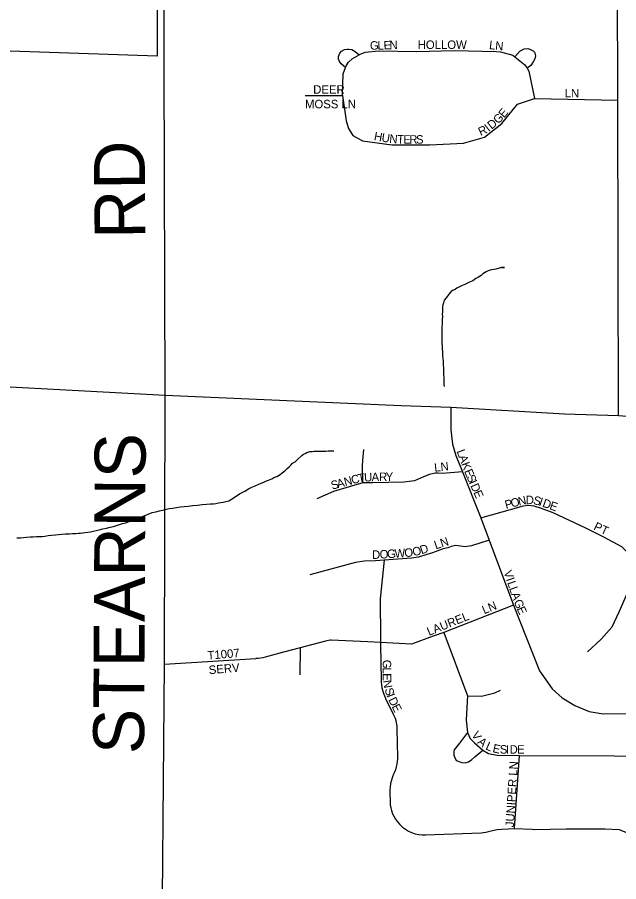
# Model space of a CAD drawing. Extents: x 2010165 to 2382125, y 1060529 to 1407316.
# Drawn here: x 2120255 to 2123802, y 1230221 to 1235321 of the extents above; entities that cross this region are included whole.
import ezdxf

# ---------------------------------------------------------------- set-up
doc = ezdxf.new("R2010")
doc.units = 0
for name, color, linetype in [('GM_X_Corporation', 7, 'Continuous'), ('GM_X_County_Road', 7, 'Continuous'), ('GM_X_County_Road_Text', 7, 'Continuous'), ('GM_X_Minor_River', 7, 'Continuous'), ('GM_X_Township_Subdivision', 7, 'Continuous'), ('GM_X_Township_Subdivision_Text', 7, 'Continuous')]:
    doc.layers.add(name, color=color, linetype=linetype)

msp = doc.modelspace()

# ---------------------------------------------------------------- linework, layer by layer
at = {"layer": 'GM_X_Corporation'}
msp.add_lwpolyline([(2132680.2, 1238887), (2124751.5, 1238922.2), (2124734, 1236210.6), (2124291.4, 1236212.5), (2123784.7, 1236210.1), (2121079.3, 1236231.2), (2121079, 1235091.9), (2120094.3, 1235126), (2120087.8, 1234155), (2113849.1, 1234218.1), (2113890.9, 1243217.2), (2116730.1, 1243190.3), (2116750.2, 1244175.2), (2120503.3, 1244150.8), (2120624.6, 1245916.3), (2121435.6, 1245924.1), (2121430.7, 1248710), (2122369.9, 1248724.5), (2122407.5, 1248826.9), (2123195.5, 1249602.9), (2123111, 1249688.7), (2124088.2, 1249725.4), (2124149.1, 1251538.9), (2132230.3, 1251466.2)], dxfattribs=at)
at = {"layer": 'GM_X_County_Road'}
for points in [[(2123800.2, 1232971.7), (2123796.3, 1234831.7), (2123792.3, 1236226.9)], [(2121121.5, 1235043), (2121118.8, 1236045)], [(2121105.1, 1229101.1), (2121104.9, 1229434.5), (2121123.1, 1231504.1), (2121126.9, 1233091.7), (2121121.5, 1235043)], [(2113843.2, 1233474.2), (2114276.3, 1233480.2), (2114757.5, 1233458.8), (2115132.4, 1233440.6), (2116121.3, 1233380.5), (2117046.3, 1233314.7), (2117603.7, 1233289.2), (2118461.7, 1233253.7), (2119661.5, 1233171.1), (2121126.9, 1233091.7), (2122519, 1233030.1), (2122811, 1233020.2), (2123481.6, 1232981.3), (2123800.2, 1232971.7), (2124805.6, 1232896), (2125621.5, 1232828), (2125767.5, 1232815.9), (2125975.7, 1232798.6), (2127217.3, 1232723), (2127635.9, 1232678.3)]]:
    msp.add_lwpolyline(points, dxfattribs=at)
at = {"layer": 'GM_X_Minor_River'}
for points in [[(2123128.9, 1233844.2), (2123110.8, 1233844.2), (2123128.9, 1233844.2), (2123110.8, 1233844.2), (2123076.7, 1233836), (2123052.6, 1233831.9), (2123042.6, 1233829.9), (2123032.6, 1233825.9), (2123020.6, 1233819.8), (2123010.6, 1233813.8), (2123000.6, 1233807.7), (2122990.6, 1233797.6), (2122974.5, 1233787.6), (2122958.5, 1233779.5), (2122940.5, 1233767.4), (2122922.5, 1233759.3), (2122894.4, 1233745.1), (2122874.4, 1233737.1), (2122858.4, 1233729), (2122846.3, 1233722.9), (2122836.3, 1233714.9), (2122826.3, 1233710.8), (2122812.3, 1233700.7), (2122800.3, 1233688.7), (2122786.3, 1233668.6), (2122772.3, 1233652.4), (2122768.4, 1233636.4), (2122764.4, 1233624.3), (2122762.4, 1233612.3), (2122762.5, 1233600.2), (2122762.5, 1233584.2), (2122760.6, 1233570.1), (2122762.6, 1233556.1), (2122760.7, 1233538), (2122760.8, 1233513.9), (2122758.8, 1233491.9), (2122758.9, 1233469.8), (2122759, 1233445.7), (2122759.1, 1233421.6), (2122759.2, 1233397.6), (2122761.2, 1233379.5), (2122761.3, 1233363.4), (2122763.3, 1233349.4), (2122763.4, 1233333.4), (2122763.4, 1233323.3), (2122763.5, 1233307.3), (2122765.5, 1233293.2), (2122765.6, 1233279.2), (2122767.7, 1233243.1), (2122767.8, 1233233), (2122767.8, 1233221), (2122767.8, 1233211), (2122769.9, 1233196.9), (2122769.9, 1233180.9), (2122770, 1233164.8), (2122770, 1233152.8), (2122772.1, 1233142.8)], [(2121369.8, 1232447.9), (2121393.9, 1232450), (2121412, 1232450.1), (2121426, 1232452.1), (2121442, 1232456.2), (2121456.1, 1232458.2), (2121468.1, 1232460.3), (2121484.1, 1232464.3), (2121502.2, 1232468.4), (2121518.2, 1232478.5), (2121540.2, 1232492.6), (2121564.3, 1232508.8), (2121596.3, 1232524.9), (2121618.3, 1232539), (2121638.4, 1232549.1), (2121658.4, 1232557.2), (2121674.4, 1232565.3), (2121692.5, 1232573.4), (2121708.5, 1232579.4), (2121724.5, 1232585.5), (2121736.6, 1232589.6), (2121746.6, 1232593.6), (2121756.6, 1232597.7), (2121768.6, 1232605.7), (2121784.6, 1232611.8), (2121794.6, 1232617.9), (2121804.7, 1232623.9), (2121814.7, 1232632), (2121826.7, 1232642), (2121836.7, 1232650.1), (2121846.7, 1232658.2), (2121858.7, 1232668.2), (2121868.7, 1232678.3), (2121878.7, 1232690.4), (2121892.7, 1232698.4), (2121906.7, 1232712.5), (2121932.7, 1232736.7), (2121942.7, 1232742.8), (2121952.7, 1232746.8), (2121962.7, 1232752.8), (2121980.8, 1232758.9), (2121992.8, 1232759), (2122004.9, 1232761), (2122018.9, 1232761.1), (2122041, 1232761.1), (2122059, 1232761.2), (2122075.1, 1232761.2), (2122089.1, 1232763.3), (2122103.2, 1232763.3), (2122115.2, 1232763.4), (2122121.2, 1232763.4)], [(2120252.8, 1232249.7), (2120272.9, 1232249.7), (2120290.9, 1232251.8), (2120309, 1232253.8), (2120331, 1232255.9), (2120349.1, 1232256), (2120367.2, 1232258.1), (2120383.2, 1232258.1), (2120401.3, 1232258.2), (2120417.3, 1232260.2), (2120437.4, 1232264.3), (2120457.4, 1232266.4), (2120479.5, 1232268.4), (2120497.5, 1232270.5), (2120517.6, 1232272.6), (2120539.7, 1232272.7), (2120561.8, 1232272.7), (2120579.8, 1232274.8), (2120599.9, 1232274.9), (2120615.9, 1232276.9), (2120628, 1232277), (2120642, 1232279), (2120654, 1232281.1), (2120670.1, 1232283.1), (2120686.1, 1232285.2), (2120702.2, 1232289.2), (2120720.2, 1232293.3), (2120738.3, 1232297.4), (2120758.3, 1232303.5), (2120780.4, 1232307.6), (2120802.4, 1232313.6), (2120822.5, 1232317.7), (2120840.5, 1232321.8), (2120858.5, 1232327.9), (2120874.6, 1232333.9), (2120894.6, 1232338), (2120928.7, 1232352.2), (2120970.8, 1232368.4), (2120992.8, 1232376.5), (2121050.9, 1232398.7), (2121071, 1232402.8), (2121093, 1232408.9), (2121119.1, 1232415), (2121135.2, 1232419.1), (2121151.2, 1232423.1), (2121169.2, 1232425.2), (2121193.3, 1232429.3), (2121215.4, 1232433.4), (2121239.4, 1232435.5), (2121261.5, 1232437.5), (2121289.6, 1232441.6), (2121317.7, 1232443.7), (2121345.8, 1232445.8), (2121369.8, 1232447.9)]]:
    msp.add_lwpolyline(points, dxfattribs=at)
at = {"layer": 'GM_X_Township_Subdivision'}
for points in [[(2122190.6, 1235025.6), (2122180.9, 1235033.2), (2122164.6, 1235046.8), (2122155.3, 1235059.9), (2122149.6, 1235074.6), (2122149.6, 1235090.4), (2122156.5, 1235109.4), (2122166.4, 1235120.9), (2122183.8, 1235131.8), (2122199.5, 1235133.9), (2122210, 1235133.4), (2122227.9, 1235130.7), (2122247.7, 1235120.3), (2122270.2, 1235099.5)], [(2122228.8, 1235075.4), (2122270.2, 1235099.5), (2122273.2, 1235101.3), (2122305.8, 1235116.5), (2122386.8, 1235122.6), (2122609.7, 1235120.4), (2122830.4, 1235124.7), (2123078.4, 1235119), (2123104.5, 1235117.3), (2123176.5, 1235098.5), (2123189.4, 1235088.4), (2123248.5, 1235041.9), (2123261.2, 1235020.4), (2123271.7, 1235002.7), (2123304.1, 1234842.9)], [(2123189.4, 1235088.4), (2123218.9, 1235121.7), (2123244.5, 1235135.8), (2123266, 1235137.2), (2123278.2, 1235133.7), (2123297.9, 1235123.8), (2123304.9, 1235115.4), (2123307.8, 1235109.4), (2123310.6, 1235094.4), (2123307.2, 1235077), (2123296.7, 1235059.6), (2123282.8, 1235037.8), (2123261.2, 1235020.4)], [(2122171.9, 1234860.1), (2122176.5, 1234988.6), (2122190.6, 1235025.6), (2122194, 1235034.6), (2122208.5, 1235056.4), (2122228.8, 1235075.4)], [(2121951.8, 1234860.7), (2122171.9, 1234860.1)], [(2122171.9, 1234860.1), (2122195.1, 1234711.4), (2122209, 1234664.6), (2122234.5, 1234624.8), (2122290.2, 1234592.1), (2122464.4, 1234568.1), (2122687.4, 1234568.1), (2122887.1, 1234579), (2123010.2, 1234613.8), (2123112.4, 1234694.3), (2123205.3, 1234809.8), (2123304.1, 1234842.9), (2123796.3, 1234831.7)], [(2122811, 1233020.2), (2122811.8, 1232887.9), (2122820.7, 1232803.3), (2122840.8, 1232735.6), (2122879.5, 1232639.2), (2122989.1, 1232368.6), (2123038.3, 1232236.4), (2123180.4, 1231852.3), (2123335, 1231465.5), (2123408.6, 1231359), (2123467.4, 1231306.5), (2123542.7, 1231260.1), (2123627.4, 1231225.6), (2123710.7, 1231211.8), (2124121.5, 1231213.9), (2124269.9, 1231213.2), (2124477.7, 1231212.6), (2124622.2, 1231190.2), (2124875.4, 1231187.9), (2124970.7, 1231187.9), (2125112.9, 1231183.4), (2125179.8, 1231182.5)], [(2122293.1, 1232574.5), (2122290.5, 1232674.5), (2122291.6, 1232705.9), (2122299.3, 1232770.9)], [(2122879.5, 1232639.2), (2122762.1, 1232629.6), (2122735.9, 1232631.8), (2122718.4, 1232630.7), (2122684.8, 1232622.9), (2122651.2, 1232610.6), (2122597.4, 1232587), (2122533.6, 1232578.1), (2122348.7, 1232573.6), (2122293.1, 1232574.5), (2122212, 1232551.2), (2122120.2, 1232524.3), (2122021.6, 1232479.5)], [(2122989.1, 1232368.6), (2123239.9, 1232438.4), (2123270.1, 1232442.9), (2123300.4, 1232439.5), (2123344.1, 1232425), (2123412.4, 1232400.3), (2123508.7, 1232354.3), (2123606.2, 1232308.4), (2123711.1, 1232256.7), (2123817.5, 1232199.5), (2123865, 1232152), (2123888.1, 1232090.8), (2123891.5, 1232033.6), (2123881.1, 1231993.8), (2123865.7, 1231955.2), (2123802.9, 1231811.7), (2123761.4, 1231722.1), (2123698.7, 1231651.5), (2123618, 1231577.5)], [(2123038.3, 1232236.4), (2122933.4, 1232202.6), (2122895.4, 1232197), (2122841, 1232203.9), (2122814.3, 1232198.3), (2122793.1, 1232191.3), (2122765.4, 1232184.7), (2122703.8, 1232161.2), (2122670.1, 1232151.1), (2122621.5, 1232136.2), (2122579.2, 1232130.5), (2122418.4, 1232117.8), (2122366.7, 1232113.7), (2122302.7, 1232111.9), (2122250, 1232105.2), (2121980, 1232032.4)], [(2122418.4, 1232117.8), (2122394.7, 1231889.7), (2122396.3, 1231656.1), (2122396.7, 1231631.8), (2122396.9, 1231618.9)], [(2123180.4, 1231852.3), (2122769.5, 1231692), (2122707.9, 1231669.4)], [(2122769.5, 1231692), (2122910.8, 1231318.4), (2122906.9, 1231248.3), (2122902.4, 1231174.3), (2122909.1, 1231100.4), (2122924.8, 1231066.8), (2122950.5, 1231041), (2123000.3, 1230997), (2123033.4, 1230978.2), (2123085, 1230967), (2123217.1, 1230965.8), (2123775.2, 1230962.8), (2123846.3, 1230961.1), (2123994.2, 1230915.2), (2124268.7, 1230915.1), (2124423.3, 1230915.1), (2124571.8, 1230963.8), (2124625.1, 1230964.5)], [(2122322.4, 1231635.4), (2122106.6, 1231646.1), (2122099, 1231645.5), (2122090, 1231644.3), (2122081.3, 1231642.7), (2122073, 1231640.7), (2121923.3, 1231600.7), (2121825.2, 1231574.4)], [(2122707.9, 1231669.4), (2122580.5, 1231622.7), (2122396.7, 1231631.8), (2122322.4, 1231635.4)], [(2121923.3, 1231600.7), (2121921.6, 1231442.1)], [(2122396.9, 1231618.9), (2122400.5, 1231411), (2122401, 1231398.2), (2122402.4, 1231383.5), (2122405.4, 1231365.3), (2122410.1, 1231345.6), (2122416.2, 1231326.8), (2122423.9, 1231308.4), (2122425.5, 1231305.2), (2122427.1, 1231301.9), (2122472.3, 1231209.3), (2122477.6, 1231197.8), (2122482.6, 1231185), (2122486.6, 1231172), (2122489.8, 1231158.2), (2122491.2, 1231150.8), (2122492.4, 1231141.5), (2122493.3, 1231131.8), (2122493.7, 1231121.4), (2122496.5, 1230955.3), (2122496.5, 1230944.2), (2122495.8, 1230932.3), (2122493.6, 1230915.1), (2122489.9, 1230897.9), (2122484.5, 1230880.4), (2122477, 1230862.4), (2122475.5, 1230859.2), (2122474, 1230856), (2122467.2, 1230839.3), (2122461.1, 1230819.9), (2122456.5, 1230800.2), (2122453.5, 1230779.7), (2122452.6, 1230767.3), (2122452.2, 1230753.2), (2122453.3, 1230690.9), (2122454.5, 1230674.9), (2122457.4, 1230657.3), (2122461.7, 1230640.5), (2122468.4, 1230621.9), (2122475.4, 1230606.8), (2122485, 1230590.2), (2122496.2, 1230574.4), (2122510.1, 1230558.6), (2122526.2, 1230543.6), (2122544.4, 1230530), (2122562.1, 1230519.6), (2122580, 1230511.4), (2122600.7, 1230504.4), (2122622.8, 1230499.5), (2122642.1, 1230497.4), (2122662.2, 1230497.1), (2122991.1, 1230508.6), (2123018.8, 1230512.6), (2123057.7, 1230522.6), (2123084.7, 1230528.3), (2123112.3, 1230531.6), (2123187, 1230534), (2123291.6, 1230530)], [(2121123.1, 1231504.1), (2121660.9, 1231537.4)], [(2121825.2, 1231574.4), (2121715.7, 1231545.1), (2121703, 1231542.1), (2121689.7, 1231539.7), (2121675.7, 1231538.2), (2121660.9, 1231537.4)], [(2122910.8, 1231318.4), (2122991.5, 1231315), (2123071, 1231336.3), (2123103.5, 1231352)], [(2122909.1, 1231100.4), (2122863.1, 1231038.7), (2122831.7, 1230999.5), (2122828.5, 1230988.7), (2122829.4, 1230967.2), (2122833, 1230956.8), (2122843.4, 1230935.2), (2122876.6, 1230924.4), (2122895.6, 1230922.2), (2122915.8, 1230928.9), (2122935.9, 1230942.4), (2122953.9, 1230958.1), (2123000.3, 1230997)], [(2123187, 1230534), (2123217.1, 1230965.8)], [(2123291.6, 1230530), (2123303.6, 1230529.5), (2123491.2, 1230532.1), (2123656.5, 1230532.1), (2123719.4, 1230533.3), (2123804.8, 1230528.1), (2123911.1, 1230486.1), (2123987.2, 1230478.2), (2124244.3, 1230478.2), (2124283.3, 1230478.2)]]:
    msp.add_lwpolyline(points, dxfattribs=at)

# ---------------------------------------------------------------- texts
at = {"layer": 'GM_X_County_Road_Text'}
for s, rotation, p in [('RD', 90.4937, (2121010.8, 1234015.4)), ('STEARNS', 89.6908, (2121001.9, 1230972.8))]:
    msp.add_text(s, height=300, rotation=rotation, dxfattribs=at).set_placement(p)
at = {"layer": 'GM_X_Township_Subdivision_Text'}
for s, rotation, p in [('G', 0.2404, (2122334.4, 1235130.2)), ('L', 1.5325, (2122379.6, 1235130.4)), ('E', 2.2468, (2122415.5, 1235131.3)), ('N', 2.2923, (2122450.7, 1235132.7)), ('HOLLOW', 0, (2122615.9, 1235134.6)), ('L', 353.0986, (2123035.2, 1235134.5)), ('N', 354.4778, (2123071.4, 1235130.1)), ('DEER', 0, (2121999.9, 1234870.6)), ('LN', 0, (2123482.7, 1234848.6)), ('MOSS LN', 0, (2121951.5, 1234784.5)), ('G', 44.7284, (2123090.5, 1234689)), ('E', 50.9466, (2123125.8, 1234724.4)), ('D', 38.3379, (2123051.5, 1234657.7)), ('H', 349.1207, (2122355.4, 1234597.3)), ('R', 24.8922, (2122987.4, 1234620.7)), ('I', 38.2733, (2123034.1, 1234644)), ('U', 350.9339, (2122400.3, 1234588.7)), ('N', 354.5604, (2122447.1, 1234581.3)), ('T', 358.1868, (2122494.4, 1234576.9)), ('E', 0, (2122531.3, 1234575.8)), ('R', 0, (2122566.5, 1234575.8)), ('S', 0, (2122606.1, 1234575.8)), ('L', 290.3706, (2122844.8, 1232761.2)), ('A', 290.3565, (2122857, 1232728.2)), ('LN', 6.0168, (2122716.1, 1232639.7)), ('K', 290.7588, (2122872.5, 1232686.6)), ('E', 292.9589, (2122888.8, 1232643.5)), ('N', 14.9167, (2122188.3, 1232554.2)), ('C', 14.922, (2122230.9, 1232565.6)), ('T', 10.4686, (2122268.1, 1232575.5)), ('U', 2.7112, (2122300.9, 1232581.7)), ('A', 1.2677, (2122344.6, 1232583.8)), ('R', 1.2941, (2122388.6, 1232584.8)), ('Y', 1.2895, (2122428.2, 1232585.7)), ('S', 293.6556, (2122902.8, 1232610.5)), ('S', 14.9209, (2122111.8, 1232533.9)), ('A', 14.8989, (2122145.8, 1232542.9)), ('I', 293.7169, (2122917, 1232578.2)), ('D', 293.7095, (2122925.8, 1232558.1)), ('E', 293.7045, (2122943.5, 1232517.8)), ('P', 14.4404, (2123137.1, 1232419.5)), ('O', 14.4466, (2123171.2, 1232428.2)), ('N', 12.3795, (2123213.4, 1232439.1)), ('D', 1.6612, (2123253.9, 1232448.2)), ('S', 346.1493, (2123294.3, 1232449.9)), ('I', 341.6342, (2123327.5, 1232441.7)), ('D', 340.4763, (2123348.1, 1232434.9)), ('E', 340.4463, (2123389.6, 1232420.2)), ('PT', 334.9823, (2123649.5, 1232300.1)), ('LN', 18.4349, (2122723, 1232181.7)), ('O', 13.2736, (2122591.2, 1232141.1)), ('D', 18.3168, (2122638.6, 1232152.5)), ('D', 2.2736, (2122348.1, 1232125)), ('O', 3.5236, (2122393.2, 1232126.8)), ('G', 3.6703, (2122437.3, 1232129.5)), ('W', 3.679, (2122481.2, 1232132.3)), ('O', 4.8812, (2122539.4, 1232136.1)), ('V', 288.86, (2123122, 1232048.2)), ('I', 288.8786, (2123136.3, 1232006.5)), ('L', 288.8707, (2123143.4, 1231985.7)), ('L', 288.8582, (2123154.8, 1231952.4)), ('A', 288.8689, (2123166.2, 1231919.1)), ('LN', 22.3798, (2123008.3, 1231798.7)), ('G', 291.8586, (2123181.4, 1231874.8)), ('E', 294.7004, (2123198.8, 1231831.5)), ('LAUREL', 21.9904, (2122682.9, 1231671.2)), ('T1007', 4.7669, (2121378.8, 1231530.9)), ('SERV', 4.7669, (2121385.9, 1231445.2)), ('G', 270.164, (2122409.7, 1231530.3)), ('L', 270.1503, (2122409.9, 1231486.3)), ('E', 270.1588, (2122410, 1231451.1)), ('N', 279.5023, (2122410.8, 1231407.1)), ('S', 287.79, (2122419.9, 1231356)), ('I', 290.4541, (2122431.5, 1231320.1)), ('D', 295.9078, (2122441.3, 1231294.7)), ('E', 296.5784, (2122460.8, 1231254.5)), ('V', 303.9265, (2122930.8, 1231087.4)), ('A', 319.877, (2122965.4, 1231039.6)), ('L', 336.6963, (2123012.7, 1231002.9)), ('E', 347.2765, (2123054.6, 1230985.9)), ('S', 359.6625, (2123100.6, 1230976.8)), ('I', 359.9941, (2123136.1, 1230976.6)), ('D', 0, (2123158.1, 1230976.6)), ('E', 0, (2123202.1, 1230976.6)), ('JUNIPER LN', 86.3314, (2123182.9, 1230541))]:
    msp.add_text(s, height=50, rotation=rotation, dxfattribs=at).set_placement(p)

doc.saveas('drawing.dxf')
